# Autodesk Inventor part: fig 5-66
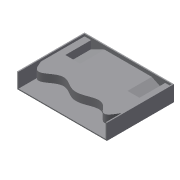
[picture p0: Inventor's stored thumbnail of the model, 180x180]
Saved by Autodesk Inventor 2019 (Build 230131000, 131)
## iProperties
Created: 2004-05
Part Number: fig 5-66
Document SubType Name: Modeling
Designer: CADCIM Technologies
Manufacturer: Standard
Standards Organization: Custom
Density: 1 g/cm^3
Material: Generic
Appearance: Default
Author: CADCIM Technologies
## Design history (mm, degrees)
sketch "Sketch1"
  geometry: L1 (-40, -30)-(40, -30); L2 (40, -30)-(40, 30); L3 (40, 30)-(-40, 30); L4 (-40, 30)-(-40, -30); 1 further point
  constraints: 8 end point, 2 parallel, 1 horizontal, 1 perpendicular, 1 other
  dimensions: "d0" = 80 distance of L1.start L1.end; "d1" = 60 distance of L3.end L1.start; "d2" = 30 distance from line of point (0, 0) L1; "d3" = 40 distance from line of point (0, 0) L4
extrude "Extrusion1" new body sketch "Sketch1" distance "d4" = 14; taper "d5" = 0 deg
shell "Shell1" dims "d6" = 1
workplane "Work Plane1"
sketch "Sketch2"
  geometry: L1 (78, -13)-(78, -11.813); L2 (0, -11.813)-(0, -13); L3 (0, -13)-(78, -13); L4 (0, -11.813)-(17.826, -3.295); L5 (17.826, -3.295)-(60.174, -3.295); L6 (60.174, -3.295)-(78, -11.813); L7 (79, -13.795)-(78, -13.795); L8 (78, 0)-(78, -13) reference; L9 (0, -13)-(0, 0) reference; L10 (78, -13)-(0, -13) reference
  constraints: 14 end point, 3 collinear, 2 equal length, 2 vertical, 1 horizontal alignment, 1 parallel, 1 point on line
extrude "Extrusion2" join sketch "Sketch2" stored distance "d8" = 14; taper "d9" = 0 deg
workplane "Work Plane2"
sketch "Sketch3"
  geometry: 7 further points
  constraints: 7 other
extrude "Extrusion7" join sketch "Sketch3" distance "d27" = 7; taper "d28" = 0 deg
body "Solid1"
other parameters: "d7" = 23, "d18" = 4, "d29" = 7
